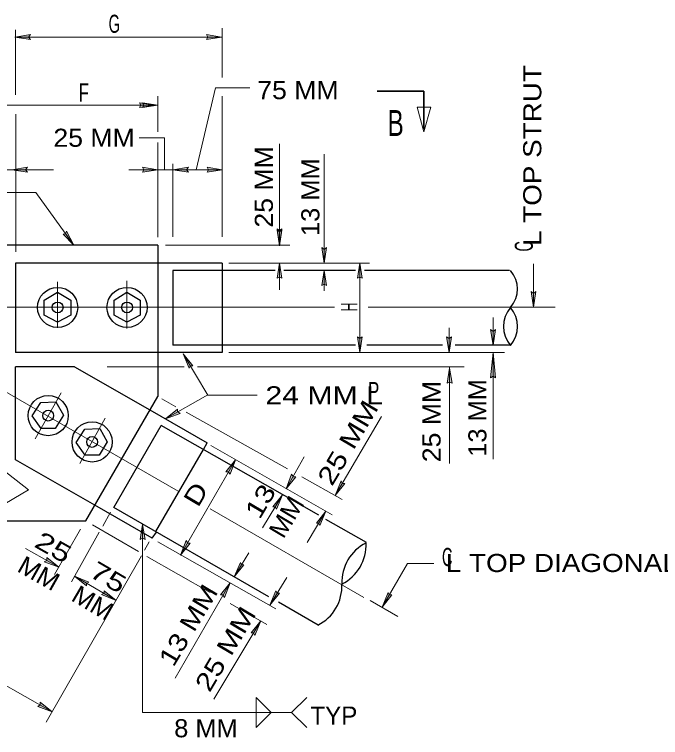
# Model space of a CAD drawing. Extents: x 312601.858 to 312602.699, y 144420.109 to 144420.704.
# Drawn here: x 312602.1711 to 312602.2782, y 144420.521 to 144420.6408 of the extents above; entities that cross this region are included whole.
import ezdxf
from ezdxf.enums import TextEntityAlignment as Align

# ---------------------------------------------------------------- set-up
doc = ezdxf.new("R2010")
doc.units = 0
doc.header["$LTSCALE"] = 0.0012
doc.linetypes.add('DOT_DASHED', pattern=[7.7, 5, -1.2, 0.3, -1.2])
doc.linetypes.add('MEDIUM_DASHED', pattern=[4.5, 3, -1.5])
for name, color, linetype, lineweight in [('1', 7, 'Continuous', 25), ('2', 7, 'Continuous', 13), ('39', 7, 'Continuous', 13), ('9', 7, 'Continuous', 13)]:
    doc.layers.add(name, color=color, linetype=linetype, lineweight=lineweight)

msp = doc.modelspace()

# ---------------------------------------------------------------- hatches: boundary and pattern name
at = {"layer": '39'}
for points in [[(312602.1734, 144420.6371), (312602.1737, 144420.6367), (312602.1711, 144420.6371), (312602.1737, 144420.6375)], [(312602.2031, 144420.6371), (312602.2029, 144420.6375), (312602.2054, 144420.6371), (312602.2029, 144420.6367)], [(312602.192, 144420.6258), (312602.1918, 144420.6262), (312602.1943, 144420.6258), (312602.1918, 144420.6254)], [(312602.1925, 144420.6258), (312602.1923, 144420.6262), (312602.1948, 144420.6258), (312602.1923, 144420.6254)], [(312602.1729, 144420.6151), (312602.1732, 144420.6147), (312602.1706, 144420.6151), (312602.1732, 144420.6155)], [(312602.1925, 144420.6151), (312602.1923, 144420.6155), (312602.1948, 144420.6151), (312602.1923, 144420.6147)], [(312602.1996, 144420.6151), (312602.1999, 144420.6147), (312602.1973, 144420.6151), (312602.1999, 144420.6155)], [(312602.2032, 144420.6151), (312602.203, 144420.6155), (312602.2055, 144420.6151), (312602.203, 144420.6147)], [(312602.2032, 144420.6151), (312602.203, 144420.6155), (312602.2055, 144420.6151), (312602.203, 144420.6147)], [(312602.1795, 144420.6045), (312602.1797, 144420.6049), (312602.1809, 144420.6026), (312602.1791, 144420.6044)], [(312602.215, 144420.605), (312602.2154, 144420.6053), (312602.215, 144420.6027), (312602.2146, 144420.6053)], [(312602.215, 144420.6048), (312602.2154, 144420.6051), (312602.215, 144420.6025), (312602.2146, 144420.6051)], [(312602.2224, 144420.6019), (312602.2228, 144420.6022), (312602.2224, 144420.5996), (312602.222, 144420.6022)], [(312602.2224, 144420.6019), (312602.2228, 144420.6022), (312602.2224, 144420.5996), (312602.222, 144420.6022)], [(312602.215, 144420.5973), (312602.2146, 144420.5971), (312602.215, 144420.5996), (312602.2154, 144420.5971)], [(312602.2283, 144420.5973), (312602.2279, 144420.5971), (312602.2283, 144420.5996), (312602.2287, 144420.5971)], [(312602.2224, 144420.5961), (312602.222, 144420.5959), (312602.2224, 144420.5984), (312602.2228, 144420.5959)], [(312602.2571, 144420.5946), (312602.2575, 144420.5949), (312602.2571, 144420.5923), (312602.2567, 144420.5949)], [(312602.2504, 144420.5883), (312602.2508, 144420.5886), (312602.2504, 144420.586), (312602.25, 144420.5886)], [(312602.2504, 144420.5883), (312602.2508, 144420.5886), (312602.2504, 144420.586), (312602.25, 144420.5886)], [(312602.2283, 144420.5871), (312602.2287, 144420.5874), (312602.2283, 144420.5848), (312602.2279, 144420.5874)], [(312602.2431, 144420.5871), (312602.2435, 144420.5874), (312602.2431, 144420.5848), (312602.2427, 144420.5874)], [(312602.2002, 144420.5826), (312602.2, 144420.5822), (312602.199, 144420.5846), (312602.2006, 144420.5826)], [(312602.2002, 144420.5826), (312602.2, 144420.5822), (312602.199, 144420.5846), (312602.2006, 144420.5826)], [(312602.2504, 144420.5809), (312602.25, 144420.5806), (312602.2504, 144420.5848), (312602.2508, 144420.5806)], [(312602.2504, 144420.5809), (312602.25, 144420.5806), (312602.2504, 144420.5848), (312602.2508, 144420.5806)], [(312602.2432, 144420.5799), (312602.2428, 144420.5797), (312602.2432, 144420.5822), (312602.2436, 144420.5797)], [(312602.1981, 144420.575), (312602.1985, 144420.5747), (312602.1961, 144420.5738), (312602.1981, 144420.5754)], [(312602.2065, 144420.565), (312602.2061, 144420.565), (312602.2077, 144420.567), (312602.2068, 144420.5646)], [(312602.2065, 144420.565), (312602.2061, 144420.565), (312602.2077, 144420.567), (312602.2068, 144420.5646)], [(312602.2173, 144420.5642), (312602.2177, 144420.5642), (312602.2161, 144420.5622), (312602.217, 144420.5646)], [(312602.2173, 144420.5642), (312602.2177, 144420.5642), (312602.2161, 144420.5622), (312602.217, 144420.5646)], [(312602.2254, 144420.5631), (312602.2258, 144420.5631), (312602.2242, 144420.5611), (312602.2252, 144420.5635)], [(312602.2254, 144420.5631), (312602.2258, 144420.5631), (312602.2242, 144420.5611), (312602.2252, 144420.5635)], [(312602.2143, 144420.5592), (312602.2139, 144420.5592), (312602.2155, 144420.5612), (312602.2145, 144420.5588)], [(312602.2143, 144420.5592), (312602.2139, 144420.5592), (312602.2155, 144420.5612), (312602.2145, 144420.5588)], [(312602.2215, 144420.5565), (312602.2211, 144420.5565), (312602.2227, 144420.5585), (312602.2217, 144420.5561)], [(312602.2215, 144420.5565), (312602.2211, 144420.5565), (312602.2227, 144420.5585), (312602.2217, 144420.5561)], [(312602.1923, 144420.554), (312602.1919, 144420.5538), (312602.1923, 144420.5563), (312602.1927, 144420.5538)], [(312602.1998, 144420.5532), (312602.2002, 144420.5532), (312602.1986, 144420.5512), (312602.1995, 144420.5536)], [(312602.1764, 144420.5503), (312602.1764, 144420.5508), (312602.1784, 144420.5492), (312602.176, 144420.5501)], [(312602.2087, 144420.5496), (312602.2091, 144420.5496), (312602.2075, 144420.5476), (312602.2085, 144420.55)], [(312602.2087, 144420.5496), (312602.2091, 144420.5496), (312602.2075, 144420.5476), (312602.2085, 144420.55)], [(312602.183, 144420.5465), (312602.183, 144420.5461), (312602.181, 144420.5477), (312602.1834, 144420.5467)], [(312602.183, 144420.5465), (312602.183, 144420.5461), (312602.181, 144420.5477), (312602.1834, 144420.5467)], [(312602.2056, 144420.5446), (312602.2052, 144420.5446), (312602.2068, 144420.5466), (312602.2059, 144420.5442)], [(312602.2056, 144420.5446), (312602.2052, 144420.5446), (312602.2068, 144420.5466), (312602.2059, 144420.5442)], [(312602.1859, 144420.5449), (312602.1859, 144420.5453), (312602.1879, 144420.5437), (312602.1855, 144420.5447)], [(312602.1859, 144420.5449), (312602.1859, 144420.5453), (312602.1879, 144420.5437), (312602.1855, 144420.5447)], [(312602.2146, 144420.5449), (312602.215, 144420.5449), (312602.2134, 144420.5429), (312602.2144, 144420.5453)], [(312602.2332, 144420.5446), (312602.2336, 144420.5446), (312602.232, 144420.5426), (312602.233, 144420.545)], [(312602.2107, 144420.5383), (312602.2103, 144420.5383), (312602.2119, 144420.5403), (312602.2109, 144420.5379)], [(312602.1753, 144420.5264), (312602.1753, 144420.5268), (312602.1773, 144420.5252), (312602.1749, 144420.5261)]]:
    msp.add_hatch(color=256, dxfattribs=at).paths.add_polyline_path(points)

# ---------------------------------------------------------------- linework, layer by layer
at = {"layer": '1', "lineweight": 13}
for p, q in [((312602.1712, 144420.6383), (312602.1712, 144420.6275)), ((312602.2055, 144420.6386), (312602.2055, 144420.6304)), ((312602.2055, 144420.6371), (312602.1713, 144420.6371)), ((312602.1948, 144420.6273), (312602.1948, 144420.6214)), ((312602.2055, 144420.6273), (312602.2055, 144420.604)), ((312602.1944, 144420.6258), (312602.1683, 144420.6258)), ((312602.1713, 144420.6243), (312602.1713, 144420.6015)), ((312602.1948, 144420.6196), (312602.1948, 144420.6039)), ((312602.215, 144420.6194), (312602.215, 144420.6025)), ((312602.2224, 144420.6177), (312602.2224, 144420.5996)), ((312602.1943, 144420.6151), (312602.19, 144420.6151)), ((312602.1973, 144420.6151), (312602.1943, 144420.6151)), ((312602.1973, 144420.6161), (312602.1973, 144420.604)), ((312602.2055, 144420.6151), (312602.1973, 144420.6151)), ((312602.2167, 144420.6026), (312602.1961, 144420.6026)), ((312602.2299, 144420.5996), (312602.2066, 144420.5996)), ((312602.215, 144420.5996), (312602.215, 144420.5952)), ((312602.2283, 144420.5996), (312602.2283, 144420.5848)), ((312602.2571, 144420.5995), (312602.2571, 144420.5923)), ((312602.2224, 144420.5984), (312602.2224, 144420.595)), ((312602.2459, 144420.5923), (312602.2607, 144420.5923)), ((312602.2504, 144420.5906), (312602.2504, 144420.586)), ((312602.2431, 144420.5889), (312602.2431, 144420.5848)), ((312602.2031, 144420.5777), (312602.199, 144420.5846)), ((312602.2523, 144420.5848), (312602.2066, 144420.5848)), ((312602.2504, 144420.5848), (312602.2504, 144420.5671)), ((312602.1992, 144420.5824), (312602.1864, 144420.5824)), ((312602.2456, 144420.5824), (312602.2014, 144420.5824)), ((312602.2432, 144420.5823), (312602.2432, 144420.5664)), ((312602.1978, 144420.5758), (312602.1955, 144420.5771)), ((312602.2031, 144420.5778), (312602.1961, 144420.5738)), ((312602.2113, 144420.5777), (312602.2031, 144420.5777)), ((312602.2163, 144420.5655), (312602.1995, 144420.5749)), ((312602.2242, 144420.5611), (312602.2319, 144420.5742)), ((312602.2237, 144420.5579), (312602.2036, 144420.5694)), ((312602.2161, 144420.5622), (312602.2191, 144420.5675)), ((312602.1986, 144420.5512), (312602.2077, 144420.567)), ((312602.2254, 144420.5604), (312602.2187, 144420.5642)), ((312602.2122, 144420.5557), (312602.2155, 144420.5612)), ((312602.1857, 144420.556), (312602.187, 144420.5583)), ((312602.2196, 144420.5533), (312602.2227, 144420.5585)), ((312602.1777, 144420.548), (312602.182, 144420.5555)), ((312602.1916, 144420.5518), (312602.184, 144420.5562)), ((312602.1805, 144420.5468), (312602.1851, 144420.555)), ((312602.1926, 144420.552), (312602.1934, 144420.5534)), ((312602.2144, 144420.5423), (312602.1948, 144420.5534)), ((312602.1784, 144420.5492), (312602.1729, 144420.5523)), ((312602.2075, 144420.5476), (312602.2099, 144420.5516)), ((312602.1763, 144420.5235), (312602.1921, 144420.5511)), ((312602.2035, 144420.545), (312602.193, 144420.551)), ((312602.1879, 144420.5437), (312602.181, 144420.5477)), ((312602.2134, 144420.5429), (312602.2162, 144420.5475)), ((312602.1977, 144420.5308), (312602.2068, 144420.5466)), ((312602.2129, 144420.5397), (312602.2068, 144420.5432)), ((312602.23, 144420.5437), (312602.2346, 144420.541)), ((312602.1773, 144420.5252), (312602.1479, 144420.542)), ((312602.2041, 144420.5273), (312602.2119, 144420.5403))]:
    msp.add_line(p, q, dxfattribs=at)
at = {"layer": '1'}
for p, q in [((312602.1948, 144420.6026), (312602.1682, 144420.6026)), ((312602.1948, 144420.6026), (312602.1948, 144420.5775)), ((312602.2055, 144420.5996), (312602.1948, 144420.5996)), ((312602.2055, 144420.5996), (312602.2055, 144420.5984)), ((312602.1973, 144420.5984), (312602.1973, 144420.586)), ((312602.2143, 144420.5984), (312602.1973, 144420.5984)), ((312602.2276, 144420.5984), (312602.2157, 144420.5984)), ((312602.2531, 144420.5984), (312602.2291, 144420.5984)), ((312602.2276, 144420.586), (312602.1973, 144420.586)), ((312602.2055, 144420.586), (312602.2055, 144420.5848)), ((312602.242, 144420.586), (312602.2295, 144420.586)), ((312602.2532, 144420.586), (312602.2441, 144420.586)), ((312602.2055, 144420.5848), (312602.1948, 144420.5848)), ((312602.1829, 144420.5569), (312602.1948, 144420.5775)), ((312602.1935, 144420.5753), (312602.203, 144420.5698)), ((312602.1875, 144420.5591), (312602.1954, 144420.5727)), ((312602.2215, 144420.5578), (312602.1954, 144420.5727)), ((312602.2024, 144420.5687), (312602.203, 144420.5698)), ((312602.1939, 144420.554), (312602.1844, 144420.5595)), ((312602.2132, 144420.5443), (312602.1875, 144420.5591)), ((312602.1688, 144420.5569), (312602.1829, 144420.5569)), ((312602.2294, 144420.5533), (312602.2227, 144420.5571)), ((312602.1939, 144420.554), (312602.1946, 144420.555)), ((312602.2214, 144420.5396), (312602.2148, 144420.5434))]:
    msp.add_line(p, q, dxfattribs=at)
at = {"layer": '1', "linetype": 'MEDIUM_DASHED'}
for p, q in [((312602.1712, 144420.5996), (312602.1712, 144420.5848)), ((312602.1948, 144420.5996), (312602.1712, 144420.5996)), ((312602.2055, 144420.5984), (312602.2055, 144420.586)), ((312602.1948, 144420.5848), (312602.1712, 144420.5848)), ((312602.1712, 144420.567), (312602.1712, 144420.5824)), ((312602.181, 144420.5824), (312602.1712, 144420.5824)), ((312602.181, 144420.5824), (312602.1935, 144420.5753)), ((312602.1945, 144420.5551), (312602.2024, 144420.5687)), ((312602.1844, 144420.5595), (312602.1712, 144420.567))]:
    msp.add_line(p, q, dxfattribs=at)
at = {"layer": '1', "linetype": 'DOT_DASHED', "lineweight": 13}
for p, q in [((312602.1782, 144420.5965), (312602.1782, 144420.5889)), ((312602.1897, 144420.5967), (312602.1897, 144420.5888)), ((312602.1405, 144420.595), (312602.1982, 144420.5618)), ((312602.1437, 144420.5923), (312602.2241, 144420.5923)), ((312602.2297, 144420.5923), (312602.2532, 144420.5923)), ((312602.1788, 144420.5781), (312602.1745, 144420.5705)), ((312602.1861, 144420.5739), (312602.1819, 144420.5664)), ((312602.2035, 144420.5589), (312602.229, 144420.5442))]:
    msp.add_line(p, q, dxfattribs=at)
at = {"layer": '1', "lineweight": 35}
msp.add_lwpolyline([(312602.2389, 144420.6218), (312602.2389, 144420.6281), (312602.2312, 144420.6281)], dxfattribs=at)
at = {"layer": '1', "lineweight": 13}
for points in [[(312602.1775, 144420.6151), (312602.1706, 144420.6151), (312602.1682, 144420.6151)], [(312602.1595, 144420.6113), (312602.1746, 144420.6113), (312602.1809, 144420.6026)], [(312602.232, 144420.5426), (312602.2362, 144420.5498), (312602.2406, 144420.5498)]]:
    msp.add_lwpolyline(points, dxfattribs=at)
at = {"layer": '1'}
for points in [[(312602.1782, 144420.5898), (312602.176, 144420.591), (312602.176, 144420.5935), (312602.1782, 144420.5948), (312602.1804, 144420.5935), (312602.1804, 144420.591)], [(312602.1897, 144420.5898), (312602.1876, 144420.591), (312602.1876, 144420.5935), (312602.1897, 144420.5948), (312602.1919, 144420.5935), (312602.1919, 144420.591)], [(312602.1779, 144420.5766), (312602.1792, 144420.5744), (312602.1778, 144420.5722), (312602.1755, 144420.5722), (312602.174, 144420.5743), (312602.1754, 144420.5765)], [(312602.1852, 144420.5722), (312602.1864, 144420.57), (312602.1851, 144420.5678), (312602.1828, 144420.5678), (312602.1813, 144420.5699), (312602.1827, 144420.5721)]]:
    msp.add_lwpolyline(points, close=True, dxfattribs=at)
for centre, radius in [((312602.1782, 144420.59227), 0.00333), ((312602.18972, 144420.59227), 0.00333), ((312602.1782, 144420.59227), 0.0009), ((312602.18972, 144420.59227), 0.0009), ((312602.176644, 144420.574333), 0.00333), ((312602.176644, 144420.574333), 0.0009), ((312602.183924, 144420.569963), 0.00333), ((312602.183924, 144420.569963), 0.0009)]:
    msp.add_circle(centre, radius, dxfattribs=at)
at = {"layer": '2'}
for points in [[(312602.2012, 144420.6151), (312602.2044, 144420.6287), (312602.2101, 144420.6287)], [(312602.1959, 144420.6151), (312602.1959, 144420.6204), (312602.1917, 144420.6204)], [(312602.1662, 144420.5676), (312602.1734, 144420.562), (312602.1682, 144420.559)], [(312602.1923, 144420.5563), (312602.1923, 144420.5251), (312602.217, 144420.5251)], [(312602.2195, 144420.5226), (312602.217, 144420.5251), (312602.2195, 144420.5276)]]:
    msp.add_lwpolyline(points, dxfattribs=at)
msp.add_lwpolyline([(312602.2111, 144420.5276), (312602.2111, 144420.5226), (312602.2136, 144420.5251)], close=True, dxfattribs=at)
at = {"layer": '2', "lineweight": 25}
for centre, start, end in [((312602.232607, 144420.546736), 116.6086, 182.56719), ((312602.222081, 144420.552915), 296.6086, 2.56719), ((312602.218072, 144420.546085), 296.6086, 2.56719)]:
    msp.add_arc(centre, 0.007275, start, end, dxfattribs=at)
for centre, major_axis, ratio in [((312602.247187, 144420.595337), (0.007275, 0), 0.772727), ((312602.259393, 144420.589116), (-0.007275, 0), 0.79798), ((312602.247187, 144420.589116), (0.007275, 0), 0.79798)]:
    msp.add_ellipse(centre, major_axis=major_axis, ratio=ratio, start_param=5.707588, end_param=6.8587826, dxfattribs=at)
at = {"layer": '39'}
for points in [[(312602.1734, 144420.6371), (312602.1737, 144420.6367), (312602.1711, 144420.6371), (312602.1737, 144420.6375)], [(312602.2031, 144420.6371), (312602.2029, 144420.6375), (312602.2054, 144420.6371), (312602.2029, 144420.6367)], [(312602.192, 144420.6258), (312602.1918, 144420.6262), (312602.1943, 144420.6258), (312602.1918, 144420.6254)], [(312602.1925, 144420.6258), (312602.1923, 144420.6262), (312602.1948, 144420.6258), (312602.1923, 144420.6254)], [(312602.1729, 144420.6151), (312602.1732, 144420.6147), (312602.1706, 144420.6151), (312602.1732, 144420.6155)], [(312602.1925, 144420.6151), (312602.1923, 144420.6155), (312602.1948, 144420.6151), (312602.1923, 144420.6147)], [(312602.1996, 144420.6151), (312602.1999, 144420.6147), (312602.1973, 144420.6151), (312602.1999, 144420.6155)], [(312602.2032, 144420.6151), (312602.203, 144420.6155), (312602.2055, 144420.6151), (312602.203, 144420.6147)], [(312602.2032, 144420.6151), (312602.203, 144420.6155), (312602.2055, 144420.6151), (312602.203, 144420.6147)], [(312602.1795, 144420.6045), (312602.1797, 144420.6049), (312602.1809, 144420.6026), (312602.1791, 144420.6044)], [(312602.215, 144420.605), (312602.2154, 144420.6053), (312602.215, 144420.6027), (312602.2146, 144420.6053)], [(312602.215, 144420.6048), (312602.2154, 144420.6051), (312602.215, 144420.6025), (312602.2146, 144420.6051)], [(312602.2224, 144420.6019), (312602.2228, 144420.6022), (312602.2224, 144420.5996), (312602.222, 144420.6022)], [(312602.2224, 144420.6019), (312602.2228, 144420.6022), (312602.2224, 144420.5996), (312602.222, 144420.6022)], [(312602.215, 144420.5973), (312602.2146, 144420.5971), (312602.215, 144420.5996), (312602.2154, 144420.5971)], [(312602.2283, 144420.5973), (312602.2279, 144420.5971), (312602.2283, 144420.5996), (312602.2287, 144420.5971)], [(312602.2224, 144420.5961), (312602.222, 144420.5959), (312602.2224, 144420.5984), (312602.2228, 144420.5959)], [(312602.2571, 144420.5946), (312602.2575, 144420.5949), (312602.2571, 144420.5923), (312602.2567, 144420.5949)], [(312602.2504, 144420.5883), (312602.2508, 144420.5886), (312602.2504, 144420.586), (312602.25, 144420.5886)], [(312602.2504, 144420.5883), (312602.2508, 144420.5886), (312602.2504, 144420.586), (312602.25, 144420.5886)], [(312602.2283, 144420.5871), (312602.2287, 144420.5874), (312602.2283, 144420.5848), (312602.2279, 144420.5874)], [(312602.2431, 144420.5871), (312602.2435, 144420.5874), (312602.2431, 144420.5848), (312602.2427, 144420.5874)], [(312602.2002, 144420.5826), (312602.2, 144420.5822), (312602.199, 144420.5846), (312602.2006, 144420.5826)], [(312602.2002, 144420.5826), (312602.2, 144420.5822), (312602.199, 144420.5846), (312602.2006, 144420.5826)], [(312602.2504, 144420.5809), (312602.25, 144420.5806), (312602.2504, 144420.5848), (312602.2508, 144420.5806)], [(312602.2504, 144420.5809), (312602.25, 144420.5806), (312602.2504, 144420.5848), (312602.2508, 144420.5806)], [(312602.2432, 144420.5799), (312602.2428, 144420.5797), (312602.2432, 144420.5822), (312602.2436, 144420.5797)], [(312602.1981, 144420.575), (312602.1985, 144420.5747), (312602.1961, 144420.5738), (312602.1981, 144420.5754)], [(312602.2065, 144420.565), (312602.2061, 144420.565), (312602.2077, 144420.567), (312602.2068, 144420.5646)], [(312602.2065, 144420.565), (312602.2061, 144420.565), (312602.2077, 144420.567), (312602.2068, 144420.5646)], [(312602.2173, 144420.5642), (312602.2177, 144420.5642), (312602.2161, 144420.5622), (312602.217, 144420.5646)], [(312602.2173, 144420.5642), (312602.2177, 144420.5642), (312602.2161, 144420.5622), (312602.217, 144420.5646)], [(312602.2254, 144420.5631), (312602.2258, 144420.5631), (312602.2242, 144420.5611), (312602.2252, 144420.5635)], [(312602.2254, 144420.5631), (312602.2258, 144420.5631), (312602.2242, 144420.5611), (312602.2252, 144420.5635)], [(312602.2143, 144420.5592), (312602.2139, 144420.5592), (312602.2155, 144420.5612), (312602.2145, 144420.5588)], [(312602.2143, 144420.5592), (312602.2139, 144420.5592), (312602.2155, 144420.5612), (312602.2145, 144420.5588)], [(312602.2215, 144420.5565), (312602.2211, 144420.5565), (312602.2227, 144420.5585), (312602.2217, 144420.5561)], [(312602.2215, 144420.5565), (312602.2211, 144420.5565), (312602.2227, 144420.5585), (312602.2217, 144420.5561)], [(312602.1923, 144420.554), (312602.1919, 144420.5538), (312602.1923, 144420.5563), (312602.1927, 144420.5538)], [(312602.1998, 144420.5532), (312602.2002, 144420.5532), (312602.1986, 144420.5512), (312602.1995, 144420.5536)], [(312602.1764, 144420.5503), (312602.1764, 144420.5508), (312602.1784, 144420.5492), (312602.176, 144420.5501)], [(312602.2087, 144420.5496), (312602.2091, 144420.5496), (312602.2075, 144420.5476), (312602.2085, 144420.55)], [(312602.2087, 144420.5496), (312602.2091, 144420.5496), (312602.2075, 144420.5476), (312602.2085, 144420.55)], [(312602.183, 144420.5465), (312602.183, 144420.5461), (312602.181, 144420.5477), (312602.1834, 144420.5467)], [(312602.183, 144420.5465), (312602.183, 144420.5461), (312602.181, 144420.5477), (312602.1834, 144420.5467)], [(312602.2056, 144420.5446), (312602.2052, 144420.5446), (312602.2068, 144420.5466), (312602.2059, 144420.5442)], [(312602.2056, 144420.5446), (312602.2052, 144420.5446), (312602.2068, 144420.5466), (312602.2059, 144420.5442)], [(312602.1859, 144420.5449), (312602.1859, 144420.5453), (312602.1879, 144420.5437), (312602.1855, 144420.5447)], [(312602.1859, 144420.5449), (312602.1859, 144420.5453), (312602.1879, 144420.5437), (312602.1855, 144420.5447)], [(312602.2146, 144420.5449), (312602.215, 144420.5449), (312602.2134, 144420.5429), (312602.2144, 144420.5453)], [(312602.2332, 144420.5446), (312602.2336, 144420.5446), (312602.232, 144420.5426), (312602.233, 144420.545)], [(312602.2107, 144420.5383), (312602.2103, 144420.5383), (312602.2119, 144420.5403), (312602.2109, 144420.5379)], [(312602.1753, 144420.5264), (312602.1753, 144420.5268), (312602.1773, 144420.5252), (312602.1749, 144420.5261)]]:
    msp.add_lwpolyline(points, close=True, dxfattribs=at)
at = {"layer": '9'}
msp.add_lwpolyline([(312602.2378, 144420.6255), (312602.2389, 144420.6214), (312602.2401, 144420.6255)], close=True, dxfattribs=at)

# ---------------------------------------------------------------- texts
at = {"layer": '2'}
for s, height, width, p in [('G', 0.003, 0.6, (312602.1876, 144420.6378)), ('F', 0.003, 0.7, (312602.18255, 144420.6264)), ('75 MM', 0.003, 1.1, (312602.21805, 144420.6268)), ('B', 0.0043, 0.7, (312602.23425, 144420.6207)), ('25 MM', 0.003, 1.1, (312602.18425, 144420.6189)), ('24 MM L', 0.003, 1.25, (312602.2224, 144420.5762)), ('P', 0.003, 0.7, (312602.2306, 144420.5769)), ('P', 0.003, 0.7, (312602.2306, 144420.5769)), ('C', 0.003, 0.6, (312602.2428, 144420.5494)), ('L TOP DIAGONAL', 0.003, 1.15, (312602.2618, 144420.5484)), ('8 MM', 0.003, 1.05, (312602.2028, 144420.521))]:
    msp.add_text(s, height=height, dxfattribs=dict(at, width=width)).set_placement(p, align=Align.CENTER)
for s, height, rotation, width, p in [('L TOP STRUT', 0.003, 90, 1.15, (312602.2584, 144420.61745)), ('25 MM', 0.003, 90, 1.1, (312602.2139, 144420.61225)), ('13 MM', 0.003, 90, 1.05, (312602.2216, 144420.61055)), ('C', 0.003, 90, 0.6, (312602.257, 144420.6024)), ('H', 0.0027, 90, 0.55, (312602.2279, 144420.59235)), ('25 MM', 0.003, 90, 1.1, (312602.2417, 144420.57335)), ('13 MM', 0.003, 90, 1.05, (312602.2493, 144420.57395)), ('25 MM', 0.003, 59.283, 1.25, (312602.227612, 144420.569084)), ('D', 0.003, 59.283, 1.25, (312602.202411, 144420.560534)), ('13', 0.003, 59.283, 1.25, (312602.213116, 144420.559384)), ('MM', 0.003, 59.283, 1.05, (312602.217432, 144420.556784)), ('25', 0.003, 330.576, 1.35, (312602.176763, 144420.551198)), ('MM', 0.003, 330.576, 1.05, (312602.174363, 144420.546872)), ('75', 0.003, 329.636, 1.35, (312602.185842, 144420.546252)), ('MM', 0.003, 329.636, 1.05, (312602.183292, 144420.541989)), ('13 MM', 0.003, 59.283, 1.2, (312602.201163, 144420.538834)), ('25 MM', 0.003, 59.283, 1.25, (312602.207312, 144420.534884))]:
    msp.add_text(s, height=height, rotation=rotation, dxfattribs=dict(at, width=width)).set_placement(p, align=Align.CENTER)
msp.add_text('TYP', height=0.003, dxfattribs=at).set_placement((312602.2201, 144420.5231))

doc.saveas('drawing.dxf')
